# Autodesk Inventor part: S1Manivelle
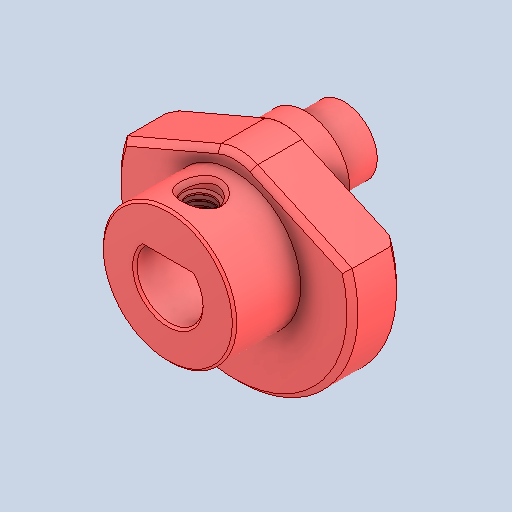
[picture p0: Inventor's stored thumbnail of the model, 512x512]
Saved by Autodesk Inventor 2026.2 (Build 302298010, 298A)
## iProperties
Created: 1601-01
Part Number: S1Manivelle
Material: 201 Annealed Stainless Steel (SS)
Document SubType Name: Modeling
Designer: mel
Density: 7.86 g/cm^3
Appearance: satin finish stainless steel
Author: mel
Sending System: SOLIDWORKS 2023
Part Number: Manivelle
Last Saved Date: 2025-04-02
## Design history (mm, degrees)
feature "Filetage2"
feature "Enlèv. mat.-Extru.9" [Filetage]
node "Plan1"
node "Plan2"
node "Solide1"
node "Solide2"
